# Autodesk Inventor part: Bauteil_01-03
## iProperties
Created: 2007-04
Part Number: Bauteil_01-03
Document SubType Name: Modeling
Designer: Sascha Fleischer
Author: Sascha Fleischer
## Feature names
1. Extrusion1
